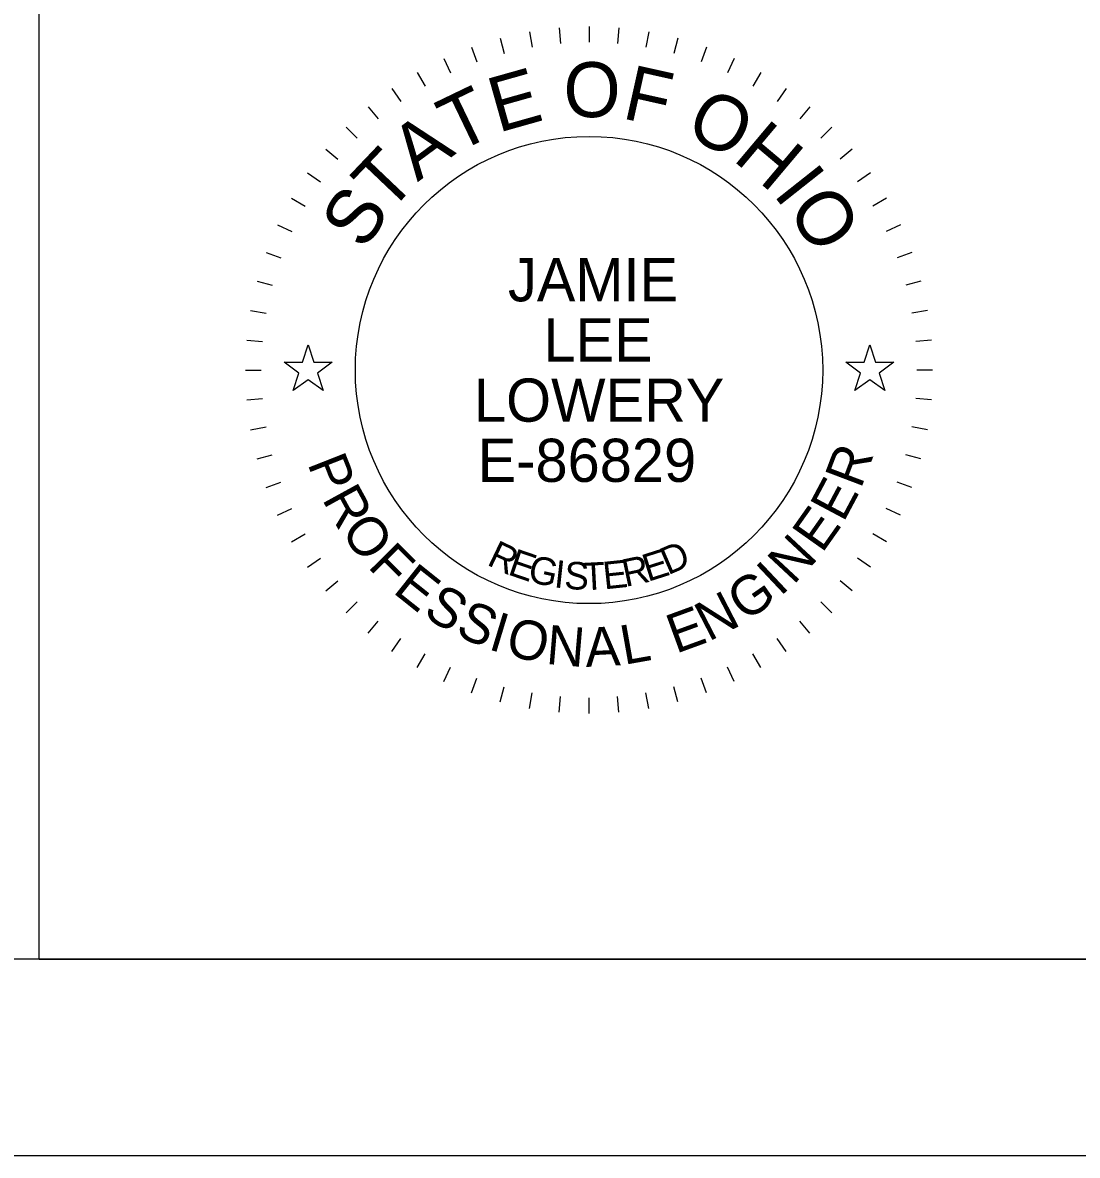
# Model space of a CAD drawing. Extents: x 0 to 34, y 0 to 22.
# Drawn here: x 7.308 to 9.993, y 0 to 2.885 of the extents above; entities that cross this region are included whole.
import ezdxf

# ---------------------------------------------------------------- set-up
doc = ezdxf.new("R2010")
doc.units = 0
for name, color, linetype in [('SH_Border', 7, 'Continuous'), ('SH_Cut_Line', 7, 'Continuous'), ('SH_Data', 7, 'Continuous'), ('SH_Seal', 7, 'Continuous')]:
    doc.layers.add(name, color=color, linetype=linetype)

msp = doc.modelspace()

# ---------------------------------------------------------------- linework, layer by layer
at = {"layer": 'SH_Border'}
msp.add_lwpolyline([(1.5, 21.5), (33.5, 21.5), (33.5, 0.5), (1.5, 0.5)], close=True, dxfattribs=at)
at = {"layer": 'SH_Cut_Line'}
msp.add_lwpolyline([(0, 0), (34, 0), (34, 22), (0, 22)], close=True, dxfattribs=at)
at = {"layer": 'SH_Data'}
for q in [(7.35, 3.75), (10.15, 0.5)]:
    msp.add_line((7.35, 0.5), q, dxfattribs=at)
at = {"layer": 'SH_Seal'}
for p, q in [((8.5981, 2.8617), (8.605, 2.8223)), ((8.6737, 2.8717), (8.6772, 2.8318)), ((8.75, 2.875), (8.75, 2.835)), ((8.8263, 2.8717), (8.8228, 2.8318)), ((8.9019, 2.8617), (8.895, 2.8223)), ((8.5235, 2.8452), (8.5339, 2.8065)), ((8.9765, 2.8452), (8.9661, 2.8065)), ((8.4507, 2.8222), (8.4644, 2.7846)), ((9.0493, 2.8222), (9.0356, 2.7846)), ((8.3802, 2.793), (8.3971, 2.7568)), ((9.1198, 2.793), (9.1029, 2.7568)), ((8.3125, 2.7578), (8.3325, 2.7231)), ((9.1875, 2.7578), (9.1675, 2.7231)), ((8.2481, 2.7168), (8.2711, 2.684)), ((9.2519, 2.7168), (9.2289, 2.684)), ((8.1876, 2.6703), (8.2133, 2.6396)), ((9.3124, 2.6703), (9.2867, 2.6396)), ((8.1313, 2.6187), (8.1596, 2.5904)), ((9.3687, 2.6187), (9.3404, 2.5904)), ((8.0797, 2.5624), (8.1104, 2.5367)), ((9.4203, 2.5624), (9.3896, 2.5367)), ((8.0332, 2.5019), (8.066, 2.4789)), ((9.4668, 2.5019), (9.434, 2.4789)), ((7.9922, 2.4375), (8.0269, 2.4175)), ((9.5078, 2.4375), (9.4731, 2.4175)), ((7.957, 2.3698), (7.9932, 2.3529)), ((9.543, 2.3698), (9.5068, 2.3529)), ((7.9278, 2.2993), (7.9654, 2.2856)), ((9.5722, 2.2993), (9.5346, 2.2856)), ((7.9048, 2.2265), (7.9435, 2.2161)), ((9.5952, 2.2265), (9.5565, 2.2161)), ((7.8883, 2.1519), (7.9277, 2.145)), ((9.6117, 2.1519), (9.5723, 2.145)), ((7.8783, 2.0763), (7.9182, 2.0728)), ((9.6217, 2.0763), (9.5818, 2.0728)), ((7.875, 2), (7.915, 2)), ((9.625, 2), (9.585, 2)), ((7.8783, 1.9237), (7.9182, 1.9272)), ((9.6217, 1.9237), (9.5818, 1.9272)), ((7.8883, 1.8481), (7.9277, 1.855)), ((9.6117, 1.8481), (9.5723, 1.855)), ((7.9048, 1.7735), (7.9435, 1.7839)), ((9.5952, 1.7735), (9.5565, 1.7839)), ((7.9278, 1.7007), (7.9654, 1.7144)), ((9.5722, 1.7007), (9.5346, 1.7144)), ((7.957, 1.6302), (7.9932, 1.6471)), ((9.543, 1.6302), (9.5068, 1.6471)), ((7.9922, 1.5625), (8.0269, 1.5825)), ((9.5078, 1.5625), (9.4731, 1.5825)), ((8.0332, 1.4981), (8.066, 1.5211)), ((9.4668, 1.4981), (9.434, 1.5211)), ((8.0797, 1.4376), (8.1104, 1.4633)), ((9.4203, 1.4376), (9.3896, 1.4633)), ((8.1313, 1.3813), (8.1596, 1.4096)), ((9.3687, 1.3813), (9.3404, 1.4096)), ((8.1876, 1.3297), (8.2133, 1.3604)), ((9.3124, 1.3297), (9.2867, 1.3604)), ((8.2481, 1.2832), (8.2711, 1.316)), ((9.2519, 1.2832), (9.2289, 1.316)), ((8.3125, 1.2422), (8.3325, 1.2769)), ((9.1875, 1.2422), (9.1675, 1.2769)), ((8.3802, 1.207), (8.3971, 1.2432)), ((9.1198, 1.207), (9.1029, 1.2432)), ((8.4507, 1.1778), (8.4644, 1.2154)), ((9.0493, 1.1778), (9.0356, 1.2154)), ((8.5235, 1.1548), (8.5339, 1.1935)), ((8.9765, 1.1548), (8.9661, 1.1935)), ((8.5981, 1.1383), (8.605, 1.1777)), ((8.6737, 1.1283), (8.6772, 1.1682)), ((8.75, 1.125), (8.75, 1.165)), ((8.8263, 1.1283), (8.8228, 1.1682)), ((8.9019, 1.1383), (8.895, 1.1777))]:
    msp.add_line(p, q, dxfattribs=at)
for points in [[(7.9736, 2.02), (8.0205, 2.02), (8.035, 2.0645), (8.0495, 2.02), (8.0964, 2.02), (8.0585, 1.9924), (8.073, 1.9478), (8.035, 1.9754), (7.997, 1.9478), (8.0115, 1.9924)], [(9.4036, 2.02), (9.4505, 2.02), (9.465, 2.0645), (9.4795, 2.02), (9.5264, 2.02), (9.4885, 1.9924), (9.503, 1.9478), (9.465, 1.9754), (9.427, 1.9478), (9.4415, 1.9924)]]:
    msp.add_lwpolyline(points, close=True, dxfattribs=at)
msp.add_circle((8.75, 2), 0.595, dxfattribs=at)

# ---------------------------------------------------------------- texts
for s, height, rotation, p in [('O', 0.14, 359.7812, (8.6847, 2.6443)), ('F', 0.14, 347.4362, (8.8311, 2.6417)), ('E', 0.14, 15.7571, (8.5184, 2.6038)), ('T', 0.14, 25.7167, (8.4116, 2.5518)), ('O', 0.14, 332.2586, (8.9898, 2.6015)), ('A', 0.14, 36.4747, (8.3134, 2.4781)), ('H', 0.14, 319.9136, (9.1132, 2.5361)), ('T', 0.14, 46.4344, (8.2383, 2.3964)), ('I', 0.14, 308.367, (9.2165, 2.4483)), ('S', 0.14, 57.1924, (8.1781, 2.3014)), ('O', 0.14, 303.1491, (9.2521, 2.4089)), ('P', 0.1, 291.494, (8.0323, 1.7621)), ('R', 0.1, 69.2322, (9.4419, 1.6954)), ('R', 0.1, 298.7311, (8.069, 1.6717)), ('E', 0.1, 61.9951, (9.3976, 1.6098)), ('E', 0.1, 54.758, (9.3433, 1.5314)), ('O', 0.1, 306.4666, (8.1155, 1.5883)), ('F', 0.1, 314.7068, (8.1843, 1.4983)), ('R', 0.07, 334.487, (8.4875, 1.5051)), ('D', 0.07, 23.3052, (8.951, 1.477)), ('N', 0.1, 47.0224, (9.2702, 1.4508)), ('E', 0.07, 341.04, (8.5406, 1.4801)), ('E', 0.07, 17.6836, (8.8998, 1.4602)), ('E', 0.1, 321.4393, (8.2478, 1.4348)), ('G', 0.07, 347.4752, (8.5914, 1.4618)), ('I', 0.07, 353.7858, (8.6591, 1.4468)), ('S', 0.07, 356.8926, (8.6858, 1.4429)), ('T', 0.07, 3.0061, (8.7357, 1.4387)), ('E', 0.07, 6.0117, (8.7889, 1.4412)), ('R', 0.07, 11.9184, (8.8425, 1.4474)), ('I', 0.1, 43.287, (9.2368, 1.4214)), ('G', 0.1, 35.0469, (9.1481, 1.357)), ('S', 0.1, 328.6764, (8.3243, 1.3752)), ('N', 0.1, 27.3113, (9.0545, 1.3075)), ('S', 0.1, 335.9134, (8.4064, 1.3266)), ('E', 0.1, 20.0742, (8.9712, 1.277)), ('I', 0.1, 343.1505, (8.4906, 1.2897)), ('O', 0.1, 346.8859, (8.5339, 1.2751)), ('N', 0.1, 355.1261, (8.6388, 1.2517)), ('A', 0.1, 2.8617, (8.7423, 1.2437)), ('L', 0.1, 10.0987, (8.8394, 1.249))]:
    msp.add_text(s, height=height, rotation=rotation, dxfattribs=at).set_placement(p)
for s, p in [('JAMIE', (8.5436, 2.1749)), ('LEE', (8.634, 2.0216)), ('LOWERY', (8.4571, 1.8684)), ('E-86829', (8.4666, 1.7151))]:
    msp.add_text(s, height=0.11, dxfattribs=at).set_placement(p)

doc.saveas('drawing.dxf')
